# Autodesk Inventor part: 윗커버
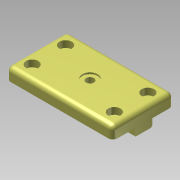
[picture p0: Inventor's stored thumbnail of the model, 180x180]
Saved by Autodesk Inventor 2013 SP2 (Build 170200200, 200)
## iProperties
Created: 2025-04
Part Number: 윗커버
Material: Generic
Document SubType Name: Modeling
Designer: i
Density: 1 g/cm^3
변환 표준: STEP AP214IS
전처리기: Build: 200, Release: 2013 SP2 Update 6 - Date: Thu 07/17/2014
전송 단위: 밀리미터
불확실성: 0.01
Author: i
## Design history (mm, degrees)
node "윗커버1"
node "솔리드1"
node "기준1"
